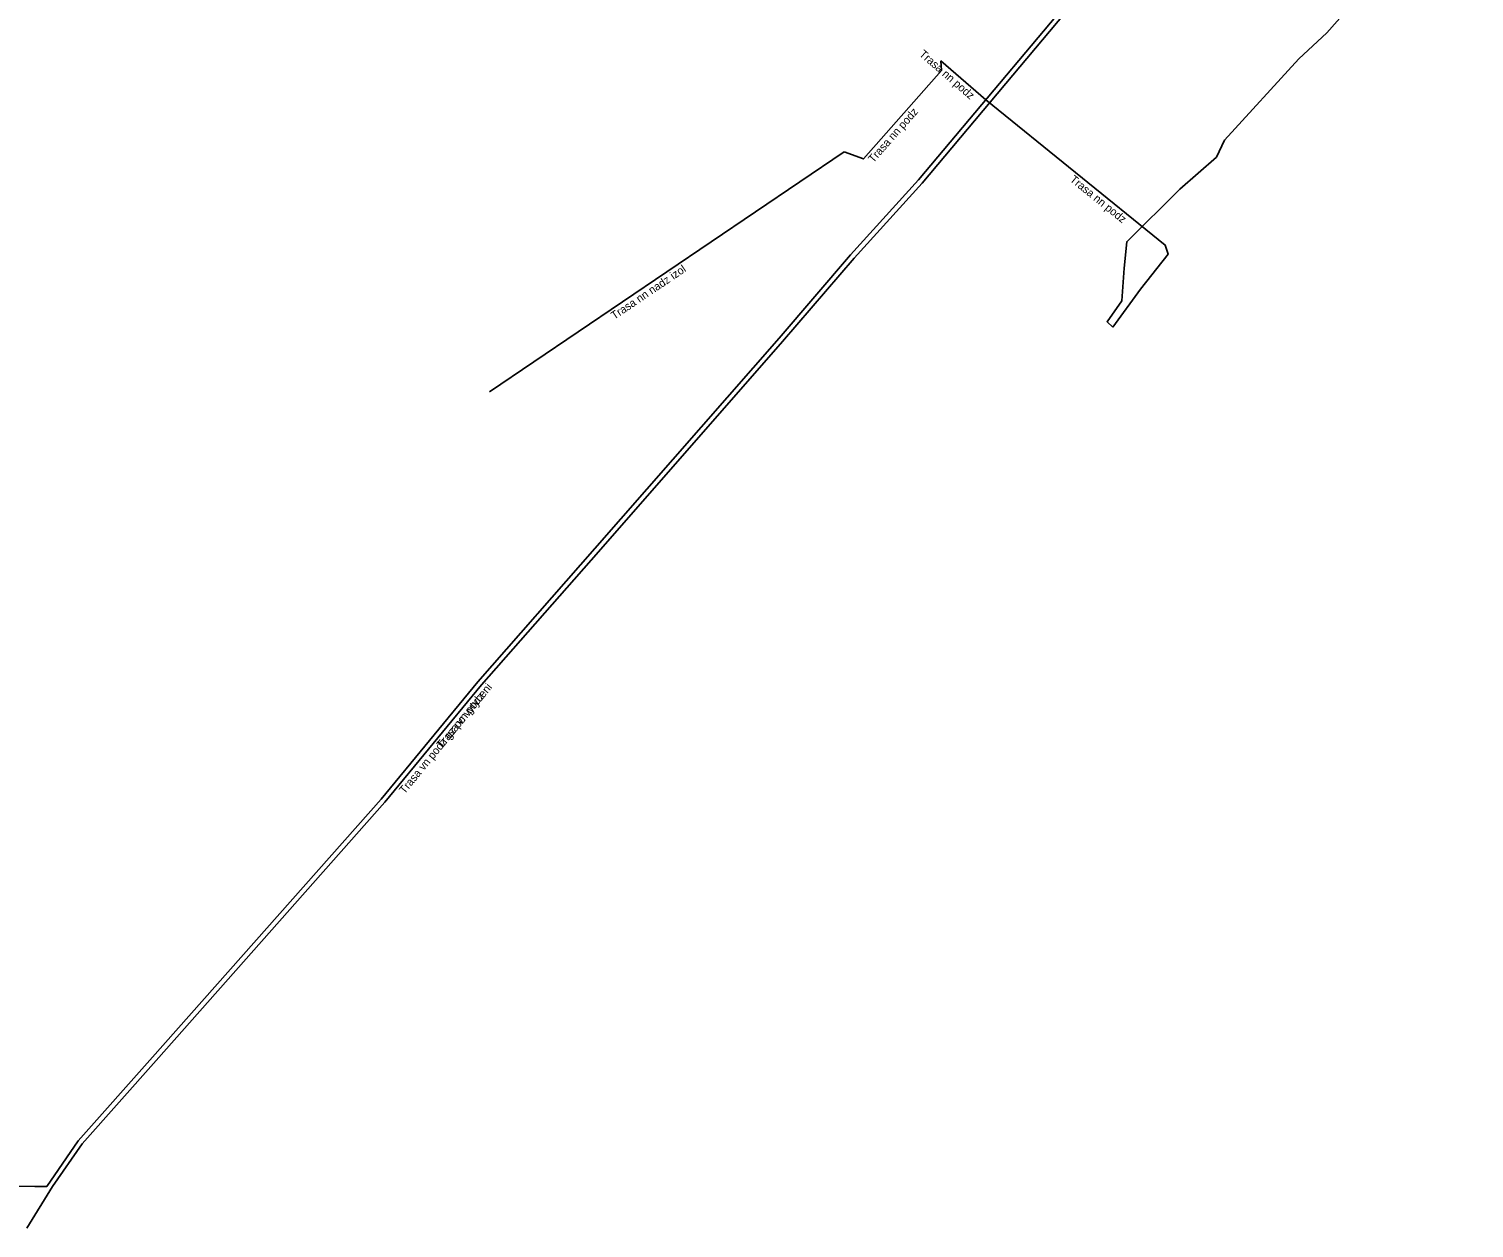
# Model space of a CAD drawing. Extents: x -764385 to -763933, y -1073568 to -1073177.
# Drawn here: x -764146.1 to -764055.8, y -1073427.8 to -1073353 of the extents above; entities that cross this region are included whole.
import ezdxf

# ---------------------------------------------------------------- set-up
doc = ezdxf.new("R2010")
doc.units = 0
for name, color, linetype in [('Popiskový text - Ostatní atributy Trasy', 7, 'Continuous'), ('Spojnice NN', 7, 'Continuous'), ('Spojnice VN', 7, 'Continuous')]:
    doc.layers.add(name, color=color, linetype=linetype)

msp = doc.modelspace()

# ---------------------------------------------------------------- linework, layer by layer
at = {"layer": 'Spojnice NN'}
for points in [[(-764078.35, -1073371.59), (-764078.71, -1073371.25), (-764077.78, -1073369.95), (-764077.63, -1073367.9), (-764077.48, -1073366.26), (-764074.16, -1073362.97), (-764071.88, -1073360.97), (-764071.38, -1073359.91), (-764066.73, -1073354.83), (-764064.97, -1073353.22), (-764061.41, -1073349.17), (-764057.28, -1073344.95), (-764053.51, -1073340.51), (-764049.09, -1073335.25), (-764048.43, -1073333.6), (-764048.53, -1073331.52), (-764047.18, -1073330.04), (-764042.57, -1073325.07), (-764038.9, -1073321.24)], [(-764095.13, -1073360.65), (-764093.927, -1073361.089), (-764089.038, -1073355.557), (-764089.079, -1073354.959)], [(-764089.079, -1073354.959), (-764086.27, -1073357.4)], [(-764078.35, -1073371.59), (-764076.61, -1073369.21), (-764074.9, -1073367.04), (-764075.07, -1073366.46), (-764086.27, -1073357.4)], [(-764095.13, -1073360.65), (-764117.29, -1073375.63)]]:
    msp.add_lwpolyline(points, dxfattribs=at)
at = {"layer": 'Spojnice VN'}
for points in [[(-764146.17, -1073427.84), (-764144.57, -1073425.25), (-764142.73, -1073422.58), (-764138.11, -1073417.37), (-764123.82, -1073401.25), (-764117.79, -1073393.92), (-764110.48, -1073385.61), (-764098.97, -1073372.48), (-764094.5, -1073367.28), (-764090.26, -1073362.59), (-764078.49, -1073348.58), (-764065.1, -1073332.87), (-764063.02, -1073330.74), (-764050.6, -1073316.09), (-764039.56, -1073303.68), (-764030.99, -1073294.01), (-764016.02, -1073276.71), (-764004.58, -1073263.98), (-763992.72, -1073249.22), (-763984.5, -1073240.06), (-763977.72, -1073232.26), (-763968.28, -1073221.76)], [(-764146.17, -1073427.84), (-764144.57, -1073425.25), (-764142.73, -1073422.58), (-764138.11, -1073417.37), (-764123.82, -1073401.25), (-764117.79, -1073393.92), (-764110.48, -1073385.61), (-764098.97, -1073372.48), (-764094.5, -1073367.28), (-764090.26, -1073362.59), (-764078.49, -1073348.58), (-764065.1, -1073332.87), (-764063.02, -1073330.74), (-764050.6, -1073316.09), (-764039.56, -1073303.68), (-764030.99, -1073294.01), (-764016.02, -1073276.71), (-764004.58, -1073263.98), (-763992.72, -1073249.22), (-763984.5, -1073240.06), (-763977.72, -1073232.26), (-763968.28, -1073221.76)], [(-764031.216, -1073293.812), (-764039.784, -1073303.481), (-764050.827, -1073315.893), (-764063.242, -1073330.538), (-764065.322, -1073332.668), (-764078.719, -1073348.386), (-764090.486, -1073362.393), (-764094.725, -1073367.082), (-764099.197, -1073372.283), (-764110.705, -1073385.412), (-764118.019, -1073393.726), (-764124.048, -1073401.055), (-764138.334, -1073417.171), (-764142.967, -1073422.395), (-764144.932, -1073425.247), (-764145.67, -1073425.242)], [(-764031.216, -1073293.812), (-764039.784, -1073303.481), (-764050.827, -1073315.893), (-764063.242, -1073330.538), (-764065.322, -1073332.668), (-764078.719, -1073348.386), (-764090.486, -1073362.393), (-764094.725, -1073367.082), (-764099.197, -1073372.283), (-764110.705, -1073385.412), (-764118.019, -1073393.726), (-764124.048, -1073401.055), (-764138.334, -1073417.171), (-764142.967, -1073422.395), (-764144.932, -1073425.247), (-764145.67, -1073425.242)], [(-764145.67, -1073425.242), (-764150, -1073425.21), (-764154.78, -1073425.46), (-764170.48, -1073421.88), (-764172.94, -1073421.21), (-764182.35, -1073417.92), (-764189.51, -1073415.77), (-764201.05, -1073412.16), (-764210.36, -1073409.89), (-764217.33, -1073407.54), (-764225.77, -1073404.79), (-764233.61, -1073402.58), (-764252.41, -1073395.89), (-764261.62, -1073392.75), (-764277.64, -1073387.2), (-764287.19, -1073382.75), (-764293.84, -1073380.18), (-764307.34, -1073375.12), (-764316.72, -1073371.94), (-764327.72, -1073368.05), (-764330.44, -1073368.57), (-764331.16, -1073370.89), (-764332.19, -1073372.8), (-764335.596, -1073378.491)], [(-764145.67, -1073425.242), (-764150, -1073425.21), (-764154.78, -1073425.46), (-764170.48, -1073421.88), (-764172.94, -1073421.21), (-764182.35, -1073417.92), (-764189.51, -1073415.77), (-764201.05, -1073412.16), (-764210.36, -1073409.89), (-764217.33, -1073407.54), (-764225.77, -1073404.79), (-764233.61, -1073402.58), (-764252.41, -1073395.89), (-764261.62, -1073392.75), (-764277.64, -1073387.2), (-764287.19, -1073382.75), (-764293.84, -1073380.18), (-764307.34, -1073375.12), (-764316.72, -1073371.94), (-764327.72, -1073368.05), (-764330.44, -1073368.57), (-764331.16, -1073370.89), (-764332.19, -1073372.8), (-764335.596, -1073378.491)]]:
    msp.add_lwpolyline(points, dxfattribs=at)

# ---------------------------------------------------------------- texts
at = {"layer": 'Popiskový text - Ostatní atributy Trasy'}
for s, rotation, p in [('Trasa nn podz', 319.0096, (-764090.477, -1073354.605)), ('Trasa nn podz', 48.53081, (-764093.305, -1073361.367)), ('Trasa nn podz', 321.02961, (-764081.071, -1073362.442)), ('Trasa nn nadz izol', 34.05841, (-764109.483, -1073371.137)), ('Trasa vn podz gz po vytyceni', 50.55769, (-764122.585, -1073400.771)), ('Trasa vn podz', 50.55769, (-764120.244, -1073397.926))]:
    msp.add_text(s, height=0.5, rotation=rotation, dxfattribs=at).set_placement(p)

doc.saveas('drawing.dxf')
